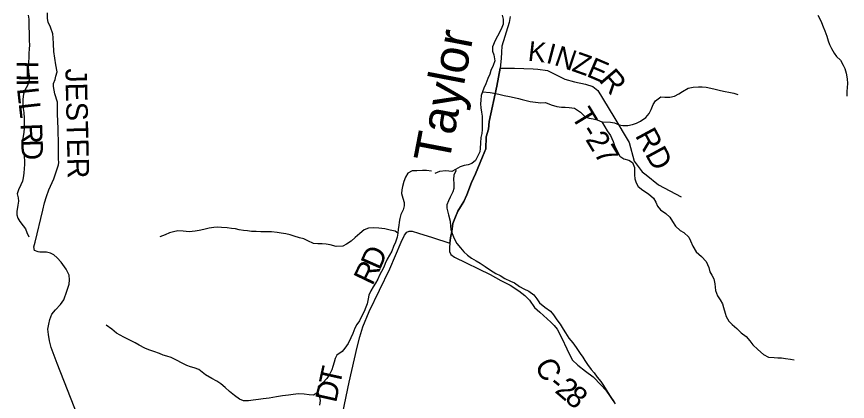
# Model space of a CAD drawing. Extents: x -139 to 835, y 0 to 440.
# Drawn here: x 472.1 to 547.7, y 235.3 to 270.4 of the extents above; entities that cross this region are included whole.
import ezdxf

# ---------------------------------------------------------------- set-up
doc = ezdxf.new("R2010")
doc.units = 0
for name, color, linetype in [('GM_X_County_Road', 7, 'Continuous'), ('GM_X_County_Road_Text', 7, 'Continuous'), ('GM_X_Minor_River', 7, 'Continuous'), ('GM_X_Minor_River_Text', 7, 'Continuous'), ('GM_X_Township_Road', 7, 'Continuous'), ('GM_X_Township_Road_Text', 7, 'Continuous')]:
    doc.layers.add(name, color=color, linetype=linetype)

msp = doc.modelspace()

# ---------------------------------------------------------------- linework, layer by layer
at = {"layer": 'GM_X_County_Road'}
for points in [[(477.62, 233.948), (475.755, 238.766), (475.194, 240.207), (475.055, 240.834), (474.966, 241.387), (474.914, 241.893), (474.979, 242.335), (475.096, 242.776), (475.278, 243.24), (475.603, 243.641), (476.061, 244.122), (476.361, 244.571), (476.643, 245.333), (476.831, 245.989), (476.881, 246.383), (476.854, 246.804), (476.568, 247.35), (476.116, 247.984), (475.761, 248.377), (475.455, 248.66), (475.133, 248.811), (474.782, 248.891), (474.495, 248.897), (474.181, 248.904), (474.012, 248.92), (473.702, 249.047), (473.62, 249.385), (473.749, 249.814), (474.444, 252.714), (474.606, 253.382), (474.78, 253.966), (475.005, 254.573), (475.438, 255.583), (475.723, 256.405), (475.879, 256.845), (475.897, 257.049), (475.88, 257.373), (475.864, 257.746), (475.859, 258.022), (475.864, 258.669), (475.839, 260.122), (475.786, 261.491), (475.775, 262.043), (475.776, 262.559), (475.549, 263.332), (475.411, 263.996), (475.432, 264.259), (475.559, 264.616), (475.633, 264.927), (475.749, 265.332), (475.636, 265.958), (475.435, 267.187), (475.427, 267.859), (475.403, 268.412), (475.349, 268.785), (475.143, 269.39), (474.934, 269.85), (474.878, 270.188), (474.866, 270.692)], [(517.013, 270.351), (516.925, 269.821), (516.249, 267.672), (516.218, 267.113), (516.194, 266.532), (516.116, 265.65)], [(516.116, 265.65), (515.804, 264.023), (515.1, 260.811), (515.038, 260.094), (514.819, 259.405), (514.788, 258.315), (514.49, 257.576), (513.849, 256.02), (513.496, 255.237), (513.065, 254.108), (512.797, 253.515), (512.508, 253.025)], [(512.508, 253.025), (512.266, 252.618), (511.97, 251.95), (511.791, 251.522), (511.719, 250.786), (511.599, 250.192), (511.527, 249.731)], [(511.527, 249.731), (511.491, 249.324), (511.491, 248.973), (511.611, 248.687), (511.935, 248.456), (515.191, 246.874), (516.184, 246.327), (517.032, 245.885), (517.822, 245.39), (518.361, 244.965), (518.766, 244.523), (519.228, 243.869), (519.71, 243.427), (520.731, 242.525), (521.04, 242.224), (521.29, 241.888), (521.714, 241.057), (522.196, 240.085), (522.677, 239.095), (523.178, 238.599), (523.891, 238.051), (524.585, 237.539), (525.317, 236.778), (525.746, 236.334), (526.581, 235.099)]]:
    msp.add_lwpolyline(points, dxfattribs=at)
at = {"layer": 'GM_X_Minor_River'}
for points in [[(473.124, 270.469), (473.158, 270.108), (473.166, 269.712), (473.174, 269.328), (473.194, 268.92), (473.216, 268.596), (473.21, 268.164), (473.217, 267.756), (473.199, 267.408), (473.181, 266.988), (473.162, 266.58), (473.144, 266.257), (473.112, 265.765), (473.131, 265.309), (473.205, 264.96), (473.213, 264.564), (473.049, 264.086), (472.821, 263.656), (472.673, 263.286), (472.614, 262.842), (472.635, 262.434), (472.668, 261.99), (472.702, 261.629), (472.734, 261.113), (472.755, 260.717), (472.747, 260.153), (472.703, 259.83), (472.659, 259.434), (472.602, 259.123), (472.545, 258.715), (472.628, 258.15), (472.728, 257.849), (472.772, 257.237), (472.767, 256.877), (472.736, 256.517), (472.717, 256.085), (472.659, 255.666), (472.603, 255.355), (472.455, 255.044), (472.24, 254.579), (472.117, 254.208), (472.191, 253.859), (472.225, 253.535), (472.181, 253.164), (472.069, 252.601), (472.065, 252.301), (472.178, 251.988), (472.344, 251.686), (472.665, 251.31), (472.857, 251.008), (472.996, 250.695), (473.16, 250.309)], [(516.295, 270.496), (516.382, 270.111), (516.376, 269.668), (516.268, 269.345), (516.12, 269.011), (515.88, 268.557), (515.64, 268.164), (515.398, 267.603), (515.406, 267.207), (515.519, 266.882), (515.617, 266.329), (515.468, 265.899), (515.266, 265.433), (515.158, 265.11), (514.996, 264.704), (514.808, 264.226), (514.62, 263.832), (514.512, 263.498), (514.39, 263.163), (514.333, 262.732), (514.316, 262.42), (514.35, 262.048), (514.397, 261.652), (514.457, 261.279), (514.479, 260.967), (514.473, 260.475), (514.455, 260.056), (514.424, 259.708), (514.354, 259.337), (514.309, 258.846), (514.29, 258.342), (514.26, 258.03), (514.112, 257.72), (513.859, 257.255), (513.516, 256.983), (513.189, 256.866), (512.836, 256.798), (512.457, 256.682), (512.037, 256.435), (511.695, 256.235), (511.149, 256.301), (510.588, 256.235), (510.143, 256.072)], [(545.044, 270.484), (545.235, 270.158), (545.387, 269.82), (545.525, 269.411), (545.677, 269.049), (545.853, 268.568), (545.978, 268.158), (546.117, 267.821), (546.295, 267.435), (546.55, 267.025), (546.755, 266.71), (547.102, 266.383), (547.37, 265.936), (547.497, 265.635), (547.622, 265.202), (547.706, 264.697), (547.74, 264.265), (547.722, 263.881), (547.692, 263.545), (547.686, 263.114)], [(514.512, 263.498), (515.189, 263.454), (515.722, 263.353), (516.112, 263.264), (516.475, 263.165), (516.956, 263.063), (517.372, 262.987), (517.775, 262.886), (518.113, 262.811), (518.477, 262.723), (518.853, 262.623), (519.321, 262.558), (519.816, 262.504), (520.246, 262.524), (520.765, 262.326), (521.284, 262.177), (521.688, 262.112), (522.026, 262.097), (522.391, 262.081), (522.885, 262.027), (523.428, 261.649), (523.853, 261.237), (524.229, 261.101), (524.58, 261.049), (524.931, 260.961), (525.358, 260.753), (526.166, 260.744), (526.53, 260.68), (526.945, 260.508), (527.283, 260.432), (527.752, 260.439), (528.157, 260.53), (528.537, 260.646), (528.904, 260.834), (529.39, 261.153), (529.682, 261.522), (529.856, 261.903), (530.057, 262.357), (530.27, 262.691), (530.757, 263.057), (531.108, 263.018), (531.577, 263), (531.982, 263.104), (532.376, 263.316), (532.704, 263.516), (533.23, 263.822), (533.687, 263.913), (534.169, 263.944), (534.509, 263.964), (534.886, 263.924), (535.315, 263.848), (535.692, 263.736), (536.185, 263.622), (536.601, 263.534), (536.952, 263.47), (537.407, 263.393), (537.77, 263.245)], [(525.358, 260.753), (525.652, 260.306), (525.869, 259.943), (526.151, 259.533), (526.404, 258.966), (526.517, 258.617), (526.784, 258.062), (527, 257.652), (527.374, 257.384), (527.842, 257.271), (528.178, 257.075), (528.342, 256.606), (528.338, 256.282), (528.346, 255.946), (528.368, 255.586), (528.493, 255.201), (528.684, 254.875), (529.111, 254.558), (529.627, 254.205), (530.091, 253.816), (530.295, 253.454), (530.434, 253.092), (530.704, 252.766), (531.194, 252.424), (531.555, 252.097), (531.811, 251.686), (532.092, 251.263), (532.504, 250.863), (532.853, 250.691), (533.291, 250.254), (533.456, 249.929), (533.671, 249.435), (533.978, 248.939), (534.442, 248.515), (534.879, 248.054), (535.106, 247.488), (535.219, 247.103), (535.397, 246.801), (535.562, 246.475), (535.674, 246.018), (535.718, 245.394), (535.894, 244.912), (536.151, 244.55), (536.355, 244.2), (536.467, 243.851), (536.591, 243.357), (536.705, 243.044), (536.934, 242.622), (537.229, 242.295), (537.668, 241.942), (538.067, 241.566), (538.532, 241.213), (538.853, 240.826), (539.122, 240.463), (539.586, 240.038), (540.101, 239.589), (540.554, 239.344), (541.062, 239.303), (541.414, 239.287), (541.752, 239.259), (542.116, 239.219), (542.546, 239.155), (542.884, 239.091)], [(509.856, 256.288), (509.413, 256.341), (509.021, 256.334), (508.524, 256.315), (508.093, 256.296), (507.712, 256.084), (507.471, 255.715), (507.336, 255.332), (507.225, 254.889), (507.142, 254.566), (507.112, 254.231), (507.236, 253.821), (507.362, 253.436), (507.357, 253.124), (507.261, 252.741), (507.059, 252.323), (506.963, 251.952), (506.906, 251.641), (506.863, 251.341), (506.832, 251.006), (506.788, 250.634), (506.717, 250.263), (506.58, 249.796), (506.405, 249.402), (506.23, 248.984), (506.042, 248.614), (505.828, 248.245), (505.64, 247.863), (505.504, 247.528), (505.303, 247.135), (505.116, 246.789), (504.967, 246.442), (504.753, 246.061), (504.54, 245.739), (504.326, 245.381), (504.151, 244.975), (504.094, 244.64), (503.983, 244.197), (503.874, 243.874), (503.712, 243.492), (503.551, 243.17), (503.283, 242.645), (503.056, 242.312), (502.869, 241.966), (502.692, 241.476), (502.504, 241.106), (502.249, 240.581), (501.956, 240.164), (501.717, 239.855), (501.242, 239.524), (501.068, 239.202), (500.985, 238.867), (500.875, 238.484), (500.767, 238.173), (500.579, 237.803), (500.325, 237.386), (499.967, 237.006), (499.518, 236.639), (499.498, 236.111), (499.611, 235.798), (499.71, 235.389), (499.652, 234.958)], [(512.037, 256.435), (512.061, 256.303), (511.9, 255.909), (511.856, 255.513), (511.903, 255.153), (511.897, 254.709), (511.802, 254.386), (511.548, 253.909), (511.401, 253.575), (511.24, 253.217), (511.249, 252.893), (511.397, 252.292), (511.547, 251.714), (511.58, 251.27), (511.615, 250.958), (511.741, 250.585), (511.905, 250.151), (512.172, 249.68), (512.506, 249.281), (512.788, 248.93), (513.123, 248.614), (513.51, 248.346), (513.912, 248.114), (514.287, 247.906), (514.739, 247.601), (515.217, 247.26), (515.721, 246.955), (516.097, 246.759), (516.549, 246.49), (517.041, 246.245), (517.404, 246.097), (517.883, 245.78), (518.257, 245.548), (518.711, 245.351), (519.163, 245.01), (519.445, 244.635), (519.701, 244.285), (520.165, 243.884), (520.682, 243.53), (520.977, 243.203), (521.271, 242.744), (521.566, 242.345), (521.834, 241.898), (522.051, 241.56), (522.371, 241.077), (522.743, 240.653), (523.025, 240.218), (523.408, 239.662), (523.639, 239.324), (523.83, 239.022), (524.073, 238.672), (524.407, 238.224), (524.676, 237.909), (524.945, 237.499), (525.279, 237.111), (525.522, 236.749), (525.764, 236.374), (526.122, 235.771), (526.454, 235.287)], [(506.788, 250.634), (506.529, 250.805), (506.099, 250.906), (505.605, 251.019), (505.07, 251.097), (504.588, 251.126), (504.104, 251.096), (503.723, 250.932), (503.327, 250.588), (502.904, 250.233), (502.547, 249.913), (502.125, 249.617), (501.77, 249.441), (501.182, 249.4), (500.623, 249.562), (500.258, 249.638), (499.893, 249.654), (499.488, 249.658), (499.097, 249.699), (498.578, 249.944), (498.228, 250.104), (497.837, 250.217), (497.356, 250.354), (496.992, 250.466), (496.589, 250.578), (496.146, 250.643), (495.807, 250.695), (495.285, 250.737), (494.319, 250.747), (493.889, 250.776), (493.458, 250.793), (493.08, 250.833), (492.715, 250.873), (492.324, 250.937), (491.985, 251.013), (491.633, 251.053), (491.229, 251.105), (490.708, 251.147), (490.355, 251.163), (490.015, 251.131), (489.597, 251.075), (489.099, 250.973), (488.68, 250.869), (488.326, 250.801), (487.777, 250.759), (487.243, 250.813), (486.76, 250.842), (486.341, 250.751), (485.974, 250.647), (485.593, 250.483), (485.094, 250.297)], [(499.498, 236.111), (499.09, 235.876), (498.712, 235.916), (498.268, 235.957), (497.733, 235.987), (497.237, 235.944), (496.831, 235.889), (496.282, 235.811), (495.719, 235.709), (495.392, 235.665), (495.051, 235.608), (494.515, 235.554), (494.096, 235.487), (493.613, 235.432), (493.181, 235.365), (492.724, 235.346), (492.373, 235.518), (491.921, 235.835), (491.456, 236.2), (491.043, 236.565), (490.656, 236.893), (490.293, 237.149), (489.84, 237.394), (489.27, 237.712), (488.663, 238.211), (488.247, 238.359), (487.909, 238.459), (487.558, 238.583), (487.143, 238.803), (486.625, 239.073), (486.131, 239.294), (485.755, 239.431), (485.417, 239.53), (485.079, 239.654), (484.559, 239.84), (484.117, 240.001), (483.728, 240.161), (483.222, 240.442), (482.86, 240.638), (482.432, 240.859), (481.835, 241.142), (481.498, 241.349), (481.161, 241.533), (480.735, 241.898), (480.205, 242.252)]]:
    msp.add_lwpolyline(points, dxfattribs=at)
at = {"layer": 'GM_X_Township_Road'}
for points in [[(512.508, 253.025), (512.797, 253.515), (513.065, 254.108), (513.496, 255.237), (513.849, 256.02), (514.49, 257.576), (514.788, 258.315), (514.819, 259.405), (515.038, 260.094), (515.1, 260.811), (515.804, 264.023), (516.116, 265.65)], [(516.116, 265.65), (517.429, 265.65), (519.124, 265.607), (519.538, 265.557), (520.413, 265.442), (522.007, 264.668), (522.882, 264.424), (523.882, 264.209), (524.554, 263.994), (524.991, 263.621), (526.476, 261.212), (527.851, 258.889), (528.328, 257.171), (529.055, 256.228), (529.424, 255.93)], [(529.424, 255.93), (530.531, 255.037), (532.597, 253.952)], [(511.527, 249.731), (511.599, 250.192), (511.719, 250.786), (511.791, 251.522), (511.97, 251.95), (512.266, 252.618), (512.508, 253.025)], [(501.612, 233.573), (502.349, 237.059), (503.091, 240.258), (503.326, 241.201), (503.612, 242.094), (504.187, 243.497), (506.068, 247.391), (507.098, 249.819), (507.385, 250.445), (507.612, 250.731), (507.816, 250.797), (508.079, 250.797), (508.654, 250.621), (509.935, 250.225), (511.527, 249.731)]]:
    msp.add_lwpolyline(points, dxfattribs=at)

# ---------------------------------------------------------------- texts
at = {"layer": 'GM_X_County_Road_Text'}
for s, height, rotation, p in [('H', 1.958, 269.5513, (472.071, 266.333)), ('JESTER', 1.9583, 271.3026, (476.495, 265.625)), ('I', 1.958, 271.65832, (472.06, 264.687)), ('L', 1.96, 276.31746, (472.091, 263.806)), ('L', 1.96, 276.41049, (472.239, 262.467)), ('R', 1.958, 272.31465, (472.419, 260.608)), ('D', 1.958, 271.63605, (472.478, 259.139)), ('C', 1.98, 297.62582, (519.205, 238.629)), ('-', 1.968, 321.07228, (520.416, 236.675)), ('2', 1.971, 319.61158, (521.01, 236.196)), ('8', 1.972, 319.58057, (521.894, 235.443))]:
    msp.add_text(s, height=height, rotation=rotation, dxfattribs=at).set_placement(p)
at = {"layer": 'GM_X_Minor_River_Text'}
msp.add_text('Taylor', height=3.2712, rotation=79.12229, dxfattribs=at).set_placement((511.422, 256.848))
at = {"layer": 'GM_X_Township_Road_Text'}
for s, height, rotation, p in [('K', 1.807, 353.57227, (518.579, 266.343)), ('I', 1.845, 345.25423, (520.21, 266.165)), ('N', 1.869, 341.29418, (520.946, 265.973)), ('Z', 1.873, 340.58491, (522.556, 265.428)), ('E', 1.896, 336.72734, (523.889, 264.959)), ('R', 1.984, 310.72631, (525.029, 264.524)), ('T-27', 1.9831, 301.37493, (522.528, 261.303)), ('RD', 1.9807, 298.36125, (528.361, 259.527)), ('D', 1.976, 66.19313, (505.135, 247.178)), ('R', 1.978, 64.29262, (504.459, 245.773)), ('T', 1.964, 77.47904, (501.502, 236.67)), ('D', 1.964, 77.50318, (501.159, 235.121))]:
    msp.add_text(s, height=height, rotation=rotation, dxfattribs=at).set_placement(p)

doc.saveas('drawing.dxf')
